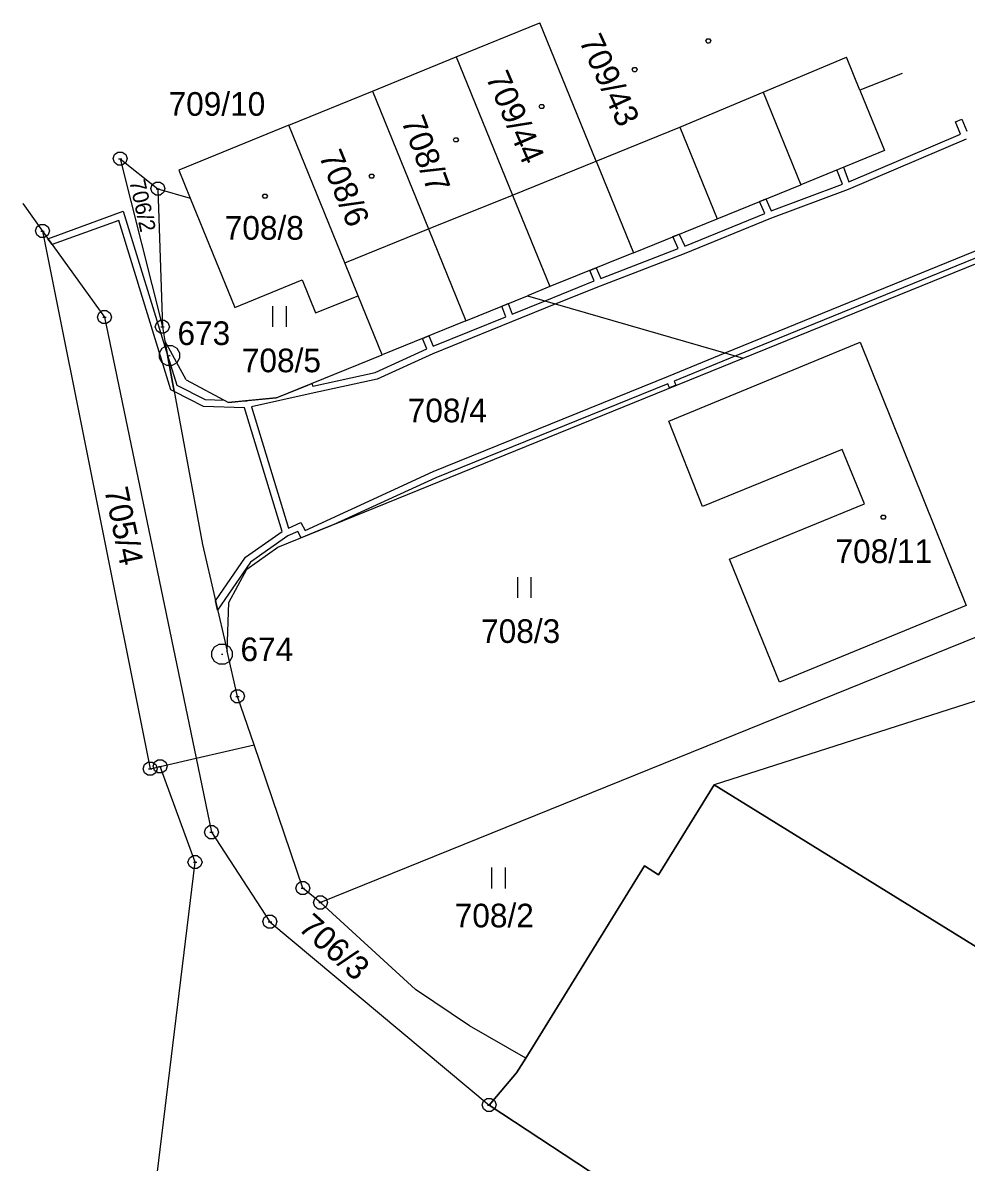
# Model space of a CAD drawing. Extents: x -759699 to -757730, y -1172308 to -1170857.
# Drawn here: x -758034.7 to -757966.9, y -1171071.6 to -1170989.6 of the extents above; entities that cross this region are included whole.
import ezdxf

# ---------------------------------------------------------------- set-up
doc = ezdxf.new("R2010")
doc.units = 0
for name, color, linetype in [('Vrstva 1', 7, 'Continuous'), ('Vrstva 11', 7, 'Continuous'), ('Vrstva 12', 7, 'Continuous'), ('Vrstva 13', 7, 'Continuous'), ('Vrstva 2', 7, 'Continuous'), ('Vrstva 3', 7, 'Continuous'), ('Vrstva 4', 7, 'Continuous'), ('Vrstva 5', 7, 'Continuous'), ('Vrstva 8', 7, 'Continuous')]:
    doc.layers.add(name, color=color, linetype=linetype)

msp = doc.modelspace()

# ---------------------------------------------------------------- linework, layer by layer
at = {"layer": 'Vrstva 1'}
for p, q in [((-758003.56, -1170992.08), (-757997.55, -1170989.62)), ((-757997.55, -1170989.62), (-757997.55, -1170989.62)), ((-757993.5, -1170999.58), (-757997.55, -1170989.62)), ((-757997.55, -1170989.62), (-757997.55, -1170989.62)), ((-758009.59, -1170994.53), (-758003.56, -1170992.08)), ((-758003.56, -1170992.08), (-758003.56, -1170992.08)), ((-758003.56, -1170992.08), (-757999.52, -1171002.02)), ((-757974.53, -1170994.46), (-757975.49, -1170992.1)), ((-757975.49, -1170992.1), (-757975.49, -1170992.1)), ((-757971.49, -1170993.27), (-757974.53, -1170994.46)), ((-757971.49, -1170993.27), (-757971.49, -1170993.27)), ((-758015.61, -1170996.99), (-758009.59, -1170994.53)), ((-758009.59, -1170994.53), (-758005.55, -1171004.46)), ((-758009.59, -1170994.53), (-758009.59, -1170994.53)), ((-757981.48, -1170994.62), (-757981.48, -1170994.62)), ((-757981.48, -1170994.62), (-757978.78, -1171001.27)), ((-757974.53, -1170994.46), (-757972.76, -1170998.82)), ((-758015.61, -1170996.99), (-758023.51, -1171000.23)), ((-758011.58, -1171006.89), (-758015.61, -1170996.99)), ((-758015.61, -1170996.99), (-758015.61, -1170996.99)), ((-757987.48, -1170997.14), (-757987.48, -1170997.14)), ((-757987.48, -1170997.14), (-757984.8, -1171003.72)), ((-757972.76, -1170998.82), (-757978.78, -1171001.27)), ((-757972.76, -1170998.82), (-757972.76, -1170998.82)), ((-758027.74, -1170999.4), (-758027.74, -1170999.4)), ((-758027.74, -1170999.4), (-758027.74, -1170999.4)), ((-758027.74, -1170999.4), (-758024.7, -1171011.5)), ((-758027.74, -1170999.4), (-758025.02, -1171001.56)), ((-758027.74, -1170999.4), (-758027.74, -1170999.4)), ((-758027.74, -1170999.4), (-758027.74, -1170999.4)), ((-757993.5, -1170999.58), (-757990.82, -1171006.17)), ((-758023.51, -1171000.23), (-758022.7, -1171002.23)), ((-758025.02, -1171001.56), (-758024.7, -1171011.5)), ((-758025.02, -1171001.56), (-758022.7, -1171002.23)), ((-757984.8, -1171003.72), (-757978.78, -1171001.27)), ((-758022.7, -1171002.23), (-758019.5, -1171010.1)), ((-757999.52, -1171002.02), (-757996.84, -1171008.61)), ((-758034.74, -1171002.63), (-758033.32, -1171004.61)), ((-758034.74, -1171002.63), (-758034.74, -1171002.63)), ((-757990.82, -1171006.17), (-757984.8, -1171003.72)), ((-758033.32, -1171004.61), (-758028.86, -1171010.81)), ((-758033.32, -1171004.61), (-758025.58, -1171043.31)), ((-758005.55, -1171004.46), (-758002.87, -1171011.06)), ((-757990.82, -1171006.17), (-757996.84, -1171008.61)), ((-758010.62, -1171009.26), (-758011.58, -1171006.89)), ((-757982.93, -1171013.75), (-757966.1, -1171006.91)), ((-758019.5, -1171010.1), (-758014.65, -1171008.13)), ((-758014.65, -1171008.13), (-758013.69, -1171010.5)), ((-757996.84, -1171008.61), (-757998.44, -1171009.26)), ((-758013.69, -1171010.5), (-758010.62, -1171009.26)), ((-758008.89, -1171013.51), (-758010.62, -1171009.26)), ((-758002.87, -1171011.06), (-757998.44, -1171009.26)), ((-757998.44, -1171009.26), (-757982.93, -1171013.75)), ((-758028.86, -1171010.81), (-758022.28, -1171042.55)), ((-758024.7, -1171011.5), (-758024.52, -1171012.5)), ((-758002.87, -1171011.06), (-758008.89, -1171013.51)), ((-758022.99, -1171015.32), (-758024.52, -1171012.5)), ((-758024.52, -1171012.5), (-758021.82, -1171027.17)), ((-757988.28, -1171018.28), (-757974.5, -1171012.6)), ((-757974.5, -1171012.6), (-757966.89, -1171031.56)), ((-758016.51, -1171016.61), (-758008.89, -1171013.51)), ((-758016.39, -1171027.36), (-757982.93, -1171013.75)), ((-758022.99, -1171015.32), (-758019.95, -1171016.94)), ((-758016.51, -1171016.61), (-758019.95, -1171016.94)), ((-757985.84, -1171024.44), (-757988.28, -1171018.28)), ((-757975.81, -1171020.32), (-757985.84, -1171024.44)), ((-757974.2, -1171024.23), (-757975.81, -1171020.32)), ((-757983.9, -1171028.22), (-757974.2, -1171024.23)), ((-758021.82, -1171027.17), (-758020.05, -1171034.85)), ((-758018.62, -1171028.95), (-758016.39, -1171027.36)), ((-757980.32, -1171037.07), (-757983.9, -1171028.22)), ((-758019.92, -1171031.35), (-758018.62, -1171028.95)), ((-757956.71, -1171029.99), (-758013.33, -1171052.94)), ((-758020.05, -1171034.85), (-758019.92, -1171031.35)), ((-757966.89, -1171031.56), (-757980.32, -1171037.07)), ((-758019.3, -1171038.1), (-758020.05, -1171034.85)), ((-757954.81, -1171034.78), (-757985.01, -1171044.46)), ((-758018.11, -1171041.59), (-758019.3, -1171038.1)), ((-758022.28, -1171042.55), (-758018.11, -1171041.59)), ((-758014.6, -1171051.9), (-758018.11, -1171041.59)), ((-758024.86, -1171043.14), (-758022.28, -1171042.55)), ((-758022.28, -1171042.55), (-758021.17, -1171047.88)), ((-758025.58, -1171043.31), (-758024.86, -1171043.14)), ((-758022.35, -1171050.03), (-758024.86, -1171043.14)), ((-757989.01, -1171050.93), (-757985.01, -1171044.46)), ((-757985.01, -1171044.46), (-757962.39, -1171058.46)), ((-758021.17, -1171047.88), (-758016.96, -1171054.32)), ((-758030.77, -1171119.52), (-758022.35, -1171050.03)), ((-757998.57, -1171064.13), (-757990.03, -1171050.3)), ((-757990.03, -1171050.3), (-757989.01, -1171050.93)), ((-758013.33, -1171052.94), (-758014.6, -1171051.9)), ((-758006.5, -1171059.2), (-758013.33, -1171052.94)), ((-758016.96, -1171054.32), (-758001.2, -1171067.51)), ((-758002.6, -1171061.8), (-758006.5, -1171059.2)), ((-757998.57, -1171064.13), (-758002.6, -1171061.8)), ((-757999.22, -1171065.2), (-757998.57, -1171064.13)), ((-758001.2, -1171067.51), (-757999.22, -1171065.2)), ((-757977.68, -1171082.98), (-758001.2, -1171067.51))]:
    msp.add_line(p, q, dxfattribs=at)
at = {"layer": 'Vrstva 11'}
for p, q in [((-757985.01, -1171044.46), (-757989.01, -1171050.93)), ((-757962.39, -1171058.46), (-757985.01, -1171044.46)), ((-757990.03, -1171050.3), (-757998.57, -1171064.13)), ((-757989.01, -1171050.93), (-757990.03, -1171050.3)), ((-757998.57, -1171064.13), (-757999.22, -1171065.2)), ((-757999.22, -1171065.2), (-758001.2, -1171067.51)), ((-758001.2, -1171067.51), (-757977.68, -1171082.98))]:
    msp.add_line(p, q, dxfattribs=at)
at = {"layer": 'Vrstva 12'}
for p, q in [((-758003.56, -1170992.08), (-757997.55, -1170989.62)), ((-757997.55, -1170989.62), (-757997.55, -1170989.62)), ((-757993.5, -1170999.58), (-757997.55, -1170989.62)), ((-757993.5, -1170999.58), (-757997.55, -1170989.62)), ((-758009.59, -1170994.53), (-758003.56, -1170992.08)), ((-758003.56, -1170992.08), (-757999.52, -1171002.02)), ((-758003.56, -1170992.08), (-757999.52, -1171002.02)), ((-757981.48, -1170994.62), (-757975.49, -1170992.1)), ((-757974.53, -1170994.46), (-757975.49, -1170992.1)), ((-757975.49, -1170992.1), (-757975.49, -1170992.1)), ((-757975.49, -1170992.1), (-757975.49, -1170992.1)), ((-757971.49, -1170993.27), (-757974.53, -1170994.46)), ((-757971.49, -1170993.27), (-757971.49, -1170993.27)), ((-758015.61, -1170996.99), (-758009.59, -1170994.53)), ((-758009.59, -1170994.53), (-758005.55, -1171004.46)), ((-758009.59, -1170994.53), (-758005.55, -1171004.46)), ((-757987.48, -1170997.14), (-757981.48, -1170994.62)), ((-757981.48, -1170994.62), (-757981.48, -1170994.62)), ((-757981.48, -1170994.62), (-757981.48, -1170994.62)), ((-758015.61, -1170996.99), (-758023.51, -1171000.23)), ((-758011.58, -1171006.89), (-758015.61, -1170996.99)), ((-758011.58, -1171006.89), (-758015.61, -1170996.99)), ((-757993.5, -1170999.58), (-757987.48, -1170997.14)), ((-757987.48, -1170997.14), (-757987.48, -1170997.14)), ((-757987.48, -1170997.14), (-757987.48, -1170997.14)), ((-757999.52, -1171002.02), (-757993.5, -1170999.58)), ((-758023.51, -1171000.23), (-758022.7, -1171002.23)), ((-758022.7, -1171002.23), (-758019.5, -1171010.1)), ((-758005.55, -1171004.46), (-757999.52, -1171002.02)), ((-758011.58, -1171006.89), (-758005.55, -1171004.46)), ((-758010.62, -1171009.26), (-758011.58, -1171006.89)), ((-758019.5, -1171010.1), (-758014.65, -1171008.13)), ((-758014.65, -1171008.13), (-758013.69, -1171010.5)), ((-758013.69, -1171010.5), (-758010.62, -1171009.26)), ((-757988.28, -1171018.28), (-757974.5, -1171012.6)), ((-757974.5, -1171012.6), (-757966.89, -1171031.56)), ((-757985.84, -1171024.44), (-757988.28, -1171018.28)), ((-757975.81, -1171020.32), (-757985.84, -1171024.44)), ((-757974.2, -1171024.23), (-757975.81, -1171020.32)), ((-757983.9, -1171028.22), (-757974.2, -1171024.23)), ((-757980.32, -1171037.07), (-757983.9, -1171028.22)), ((-757966.89, -1171031.56), (-757980.32, -1171037.07))]:
    msp.add_line(p, q, dxfattribs=at)
at = {"layer": 'Vrstva 13'}
for p, q in [((-757967.65, -1170996.74), (-757967.19, -1170996.55)), ((-757967.3, -1170997.63), (-757967.65, -1170996.74)), ((-757967.19, -1170996.55), (-757966.84, -1170997.43)), ((-757966.88, -1170997.99), (-757975.37, -1171001.62)), ((-757975.32, -1171001.06), (-757967.3, -1170997.63)), ((-757976.18, -1171000.21), (-757975.72, -1171000.02)), ((-757975.72, -1171000.02), (-757975.32, -1171001.06)), ((-757975.78, -1171001.24), (-757976.18, -1171000.21)), ((-757975.37, -1171001.62), (-757980.95, -1171003.7)), ((-757980.91, -1171003.15), (-757975.78, -1171001.24)), ((-757981.75, -1171002.48), (-757981.29, -1171002.29)), ((-757981.37, -1171003.34), (-757981.75, -1171002.48)), ((-757981.29, -1171002.29), (-757980.91, -1171003.15)), ((-758032.93, -1171005.16), (-758027.51, -1171003.18)), ((-758027.51, -1171003.18), (-758024.33, -1171013.55)), ((-757987.13, -1171005.69), (-757981.37, -1171003.34)), ((-758027.83, -1171003.84), (-758032.62, -1171005.58)), ((-758024.09, -1171016.03), (-758027.83, -1171003.84)), ((-757980.95, -1171003.7), (-757987.17, -1171006.24)), ((-757987.98, -1171005.01), (-757987.52, -1171004.83)), ((-757987.52, -1171004.83), (-757987.13, -1171005.69)), ((-758032.62, -1171005.58), (-758032.93, -1171005.16)), ((-757987.6, -1171005.87), (-757987.98, -1171005.01)), ((-757984.22, -1171013.38), (-757963.99, -1171005.12)), ((-757963.81, -1171005.58), (-757983.45, -1171013.6)), ((-757987.17, -1171006.24), (-757993.22, -1171008.57)), ((-757993.17, -1171008.02), (-757987.6, -1171005.87)), ((-757993.96, -1171007.44), (-757993.5, -1171007.25)), ((-757993.64, -1171008.2), (-757993.96, -1171007.44)), ((-757993.5, -1171007.25), (-757993.17, -1171008.02)), ((-757997.17, -1171009.63), (-757993.64, -1171008.2)), ((-757993.22, -1171008.57), (-757996.39, -1171009.85)), ((-758000.29, -1171010.01), (-757999.83, -1171009.82)), ((-757999.83, -1171009.82), (-757999.53, -1171010.58)), ((-757996.39, -1171009.85), (-757999.58, -1171011.14)), ((-757999.53, -1171010.58), (-757997.17, -1171009.63)), ((-757999.99, -1171010.77), (-758000.29, -1171010.01)), ((-757999.58, -1171011.14), (-758005.25, -1171013.45)), ((-758005.22, -1171012.9), (-757999.99, -1171010.77)), ((-758005.99, -1171012.33), (-758005.54, -1171012.15)), ((-758005.67, -1171013.09), (-758005.99, -1171012.33)), ((-758005.54, -1171012.15), (-758005.22, -1171012.9)), ((-758009.4, -1171014.79), (-758005.67, -1171013.09)), ((-758024.33, -1171013.55), (-758023.85, -1171016.16)), ((-758023.85, -1171016.16), (-758024.33, -1171013.55)), ((-758024.33, -1171013.55), (-758023.67, -1171015.69)), ((-758005.25, -1171013.45), (-758009.24, -1171015.27)), ((-757988.29, -1171015.04), (-757984.22, -1171013.38)), ((-757983.45, -1171013.6), (-757987.88, -1171015.41)), ((-758013.88, -1171015.76), (-758009.4, -1171014.79)), ((-758014.41, -1171015.76), (-758013.95, -1171015.57)), ((-758009.24, -1171015.27), (-758013.99, -1171016.29)), ((-758013.95, -1171015.57), (-758013.88, -1171015.76)), ((-758005.23, -1171021.92), (-757988.29, -1171015.04)), ((-757988.34, -1171015.6), (-758005.03, -1171022.38)), ((-757988.22, -1171015.9), (-757988.34, -1171015.6)), ((-757987.88, -1171015.41), (-757987.76, -1171015.71)), ((-758023.85, -1171016.16), (-758024.09, -1171016.03)), ((-758021.75, -1171017.24), (-758023.85, -1171016.16)), ((-758023.67, -1171015.69), (-758021.63, -1171016.74)), ((-758013.99, -1171016.29), (-758018.29, -1171017.26)), ((-758016.51, -1171016.61), (-758014.41, -1171015.76)), ((-757987.76, -1171015.71), (-757988.22, -1171015.9)), ((-758018.8, -1171017.32), (-758021.75, -1171017.24)), ((-758021.63, -1171016.74), (-758020.25, -1171016.78)), ((-758020.25, -1171016.78), (-758019.95, -1171016.94)), ((-758019.95, -1171016.94), (-758018.76, -1171016.83)), ((-758018.76, -1171016.83), (-758018.63, -1171016.83)), ((-758018.63, -1171016.83), (-758018.52, -1171016.8)), ((-758018.52, -1171016.8), (-758016.51, -1171016.61)), ((-758018.29, -1171017.26), (-758015.63, -1171025.98)), ((-758016.08, -1171026.22), (-758018.8, -1171017.32)), ((-758014.43, -1171026.15), (-758005.23, -1171021.92)), ((-758005.03, -1171022.38), (-758012.42, -1171025.74)), ((-758018.73, -1171028.07), (-758016.08, -1171026.22)), ((-758014.96, -1171026.22), (-758015.67, -1171026.54)), ((-758015.63, -1171025.98), (-758014.74, -1171025.58)), ((-758014.72, -1171026.68), (-758014.96, -1171026.22)), ((-758014.74, -1171025.58), (-758014.43, -1171026.15)), ((-758013.45, -1171026.16), (-758014.72, -1171026.68)), ((-758012.42, -1171025.74), (-758013.45, -1171026.16)), ((-758015.67, -1171026.54), (-758018.37, -1171028.43)), ((-758020.88, -1171031.23), (-758018.73, -1171028.07)), ((-758018.37, -1171028.43), (-758020.73, -1171031.89)), ((-758020.73, -1171031.89), (-758020.88, -1171031.23))]:
    msp.add_line(p, q, dxfattribs=at)
at = {"layer": 'Vrstva 3'}
for p, q in [((-758016.78, -1171010.01), (-758016.78, -1171011.51)), ((-758015.78, -1171011.51), (-758015.78, -1171010.01)), ((-757999.17, -1171029.51), (-757999.17, -1171031.01)), ((-757998.17, -1171031.01), (-757998.17, -1171029.51)), ((-758001.03, -1171050.42), (-758001.03, -1171051.92)), ((-758000.03, -1171051.92), (-758000.03, -1171050.42))]:
    msp.add_line(p, q, dxfattribs=at)
at = {"layer": 'Vrstva 4'}
for p, q in [((-757981.48, -1170994.62), (-757975.49, -1170992.1)), ((-757987.48, -1170997.14), (-757981.48, -1170994.62)), ((-757993.5, -1170999.58), (-757987.48, -1170997.14)), ((-757999.52, -1171002.02), (-757993.5, -1170999.58)), ((-758005.55, -1171004.46), (-757999.52, -1171002.02)), ((-758011.58, -1171006.89), (-758005.55, -1171004.46))]:
    msp.add_line(p, q, dxfattribs=at)
at = {"layer": 'Vrstva 5'}
for points in [[(-757985.34, -1170990.78), (-757985.25, -1170990.93), (-757985.34, -1170991.08), (-757985.52, -1170991.08), (-757985.61, -1170990.93), (-757985.52, -1170990.78)], [(-757990.64, -1170992.84), (-757990.55, -1170992.99), (-757990.64, -1170993.14), (-757990.82, -1170993.14), (-757990.91, -1170992.99), (-757990.82, -1170992.84)], [(-757997.34, -1170995.49), (-757997.25, -1170995.64), (-757997.34, -1170995.79), (-757997.52, -1170995.79), (-757997.61, -1170995.64), (-757997.52, -1170995.49)], [(-758003.5, -1170997.89), (-758003.41, -1170998.04), (-758003.5, -1170998.19), (-758003.68, -1170998.19), (-758003.77, -1170998.04), (-758003.68, -1170997.89)], [(-758009.56, -1171000.51), (-758009.47, -1171000.66), (-758009.56, -1171000.81), (-758009.74, -1171000.81), (-758009.83, -1171000.66), (-758009.74, -1171000.51)], [(-758017.23, -1171001.95), (-758017.14, -1171002.1), (-758017.23, -1171002.25), (-758017.41, -1171002.25), (-758017.5, -1171002.1), (-758017.41, -1171001.95)], [(-757972.75, -1171025.05), (-757972.66, -1171025.2), (-757972.75, -1171025.35), (-757972.93, -1171025.35), (-757973.02, -1171025.2), (-757972.93, -1171025.05)]]:
    msp.add_lwpolyline(points, close=True, dxfattribs=at)
at = {"layer": 'Vrstva 8'}
for p, q in [((-758027.86, -1170999.4), (-758027.62, -1170999.4)), ((-758025.14, -1171001.56), (-758024.9, -1171001.56)), ((-758033.44, -1171004.61), (-758033.2, -1171004.61)), ((-758028.98, -1171010.81), (-758028.74, -1171010.81)), ((-758024.82, -1171011.5), (-758024.58, -1171011.5)), ((-758024.23, -1171013.56), (-758024.13, -1171013.56)), ((-758020.46, -1171035.05), (-758020.36, -1171035.05)), ((-758019.42, -1171038.1), (-758019.18, -1171038.1)), ((-758025.7, -1171043.31), (-758025.46, -1171043.31)), ((-758024.98, -1171043.14), (-758024.74, -1171043.14)), ((-758021.29, -1171047.88), (-758021.05, -1171047.88)), ((-758022.47, -1171050.03), (-758022.23, -1171050.03)), ((-758014.72, -1171051.9), (-758014.48, -1171051.9)), ((-758013.45, -1171052.94), (-758013.21, -1171052.94)), ((-758017.08, -1171054.32), (-758016.84, -1171054.32)), ((-758001.32, -1171067.51), (-758001.08, -1171067.51))]:
    msp.add_line(p, q, dxfattribs=at)
for points in [[(-758027.59, -1170998.92), (-758027.34, -1170999.1), (-758027.24, -1170999.39), (-758027.34, -1170999.68), (-758027.59, -1170999.86), (-758027.9, -1170999.86), (-758028.15, -1170999.68), (-758028.25, -1170999.39), (-758028.15, -1170999.1), (-758027.9, -1170998.92)], [(-758024.87, -1171001.08), (-758024.62, -1171001.26), (-758024.52, -1171001.55), (-758024.62, -1171001.84), (-758024.87, -1171002.02), (-758025.18, -1171002.02), (-758025.43, -1171001.84), (-758025.53, -1171001.55), (-758025.43, -1171001.26), (-758025.18, -1171001.08)], [(-758033.17, -1171004.13), (-758032.92, -1171004.31), (-758032.82, -1171004.6), (-758032.92, -1171004.89), (-758033.17, -1171005.07), (-758033.48, -1171005.07), (-758033.73, -1171004.89), (-758033.83, -1171004.6), (-758033.73, -1171004.31), (-758033.48, -1171004.13)], [(-758028.71, -1171010.33), (-758028.46, -1171010.51), (-758028.36, -1171010.8), (-758028.46, -1171011.09), (-758028.71, -1171011.27), (-758029.02, -1171011.27), (-758029.27, -1171011.09), (-758029.37, -1171010.8), (-758029.27, -1171010.51), (-758029.02, -1171010.33)], [(-758024.55, -1171011.02), (-758024.3, -1171011.2), (-758024.2, -1171011.49), (-758024.3, -1171011.78), (-758024.55, -1171011.96), (-758024.86, -1171011.96), (-758025.11, -1171011.78), (-758025.21, -1171011.49), (-758025.11, -1171011.2), (-758024.86, -1171011.02)], [(-758023.99, -1171012.84), (-758023.65, -1171013.03), (-758023.46, -1171013.37), (-758023.46, -1171013.76), (-758023.65, -1171014.1), (-758023.99, -1171014.29), (-758024.38, -1171014.29), (-758024.72, -1171014.1), (-758024.91, -1171013.76), (-758024.91, -1171013.37), (-758024.72, -1171013.03), (-758024.38, -1171012.84)], [(-758020.22, -1171034.33), (-758019.88, -1171034.52), (-758019.69, -1171034.86), (-758019.69, -1171035.25), (-758019.88, -1171035.59), (-758020.22, -1171035.78), (-758020.61, -1171035.78), (-758020.95, -1171035.59), (-758021.14, -1171035.25), (-758021.14, -1171034.86), (-758020.95, -1171034.52), (-758020.61, -1171034.33)], [(-758019.15, -1171037.62), (-758018.9, -1171037.8), (-758018.8, -1171038.09), (-758018.9, -1171038.38), (-758019.15, -1171038.56), (-758019.46, -1171038.56), (-758019.71, -1171038.38), (-758019.81, -1171038.09), (-758019.71, -1171037.8), (-758019.46, -1171037.62)], [(-758024.71, -1171042.66), (-758024.46, -1171042.84), (-758024.36, -1171043.13), (-758024.46, -1171043.42), (-758024.71, -1171043.6), (-758025.02, -1171043.6), (-758025.27, -1171043.42), (-758025.37, -1171043.13), (-758025.27, -1171042.84), (-758025.02, -1171042.66)], [(-758025.43, -1171042.83), (-758025.18, -1171043.01), (-758025.08, -1171043.3), (-758025.18, -1171043.59), (-758025.43, -1171043.77), (-758025.74, -1171043.77), (-758025.99, -1171043.59), (-758026.09, -1171043.3), (-758025.99, -1171043.01), (-758025.74, -1171042.83)], [(-758021.02, -1171047.4), (-758020.77, -1171047.58), (-758020.67, -1171047.87), (-758020.77, -1171048.16), (-758021.02, -1171048.34), (-758021.33, -1171048.34), (-758021.58, -1171048.16), (-758021.68, -1171047.87), (-758021.58, -1171047.58), (-758021.33, -1171047.4)], [(-758022.2, -1171049.55), (-758021.95, -1171049.73), (-758021.85, -1171050.02), (-758021.95, -1171050.31), (-758022.2, -1171050.49), (-758022.51, -1171050.49), (-758022.76, -1171050.31), (-758022.86, -1171050.02), (-758022.76, -1171049.73), (-758022.51, -1171049.55)], [(-758014.45, -1171051.42), (-758014.2, -1171051.6), (-758014.1, -1171051.89), (-758014.2, -1171052.18), (-758014.45, -1171052.36), (-758014.76, -1171052.36), (-758015.01, -1171052.18), (-758015.11, -1171051.89), (-758015.01, -1171051.6), (-758014.76, -1171051.42)], [(-758013.18, -1171052.46), (-758012.93, -1171052.64), (-758012.83, -1171052.93), (-758012.93, -1171053.22), (-758013.18, -1171053.4), (-758013.49, -1171053.4), (-758013.74, -1171053.22), (-758013.84, -1171052.93), (-758013.74, -1171052.64), (-758013.49, -1171052.46)], [(-758016.81, -1171053.84), (-758016.56, -1171054.02), (-758016.46, -1171054.31), (-758016.56, -1171054.6), (-758016.81, -1171054.78), (-758017.12, -1171054.78), (-758017.37, -1171054.6), (-758017.47, -1171054.31), (-758017.37, -1171054.02), (-758017.12, -1171053.84)], [(-758001.05, -1171067.03), (-758000.8, -1171067.21), (-758000.7, -1171067.5), (-758000.8, -1171067.79), (-758001.05, -1171067.97), (-758001.36, -1171067.97), (-758001.61, -1171067.79), (-758001.71, -1171067.5), (-758001.61, -1171067.21), (-758001.36, -1171067.03)]]:
    msp.add_lwpolyline(points, close=True, dxfattribs=at)

# ---------------------------------------------------------------- texts
at = {"layer": 'Vrstva 2'}
for s, height, rotation, p in [('709/43', 1.7, 294.6149, (-757994.761, -1170990.916)), ('709/44', 1.7, 293.2398, (-758001.466, -1170993.538)), ('708/7', 1.7, 290.5469, (-758007.537, -1170996.682)), ('708/6', 1.7, 292.20848, (-758013.47, -1170999.19)), ('706/2', 1.14, 282.4109, (-758027.083, -1171001.032)), ('705/4', 1.7, 281.89524, (-758028.885, -1171023.218)), ('706/3', 1.7, 318.04887, (-758015.008, -1171054.846))]:
    msp.add_text(s, height=height, rotation=rotation, dxfattribs=at).set_placement(p)
for s, p in [('709/10', (-758024.253, -1170996.31)), ('708/8', (-758020.213, -1171005.23)), ('708/5', (-758018.983, -1171014.77)), ('708/4', (-758007.053, -1171018.37)), ('708/11', (-757976.283, -1171028.5)), ('708/3', (-758001.773, -1171034.25)), ('708/2', (-758003.673, -1171054.72))]:
    msp.add_text(s, height=1.7, dxfattribs=at).set_placement(p)
at = {"layer": 'Vrstva 8'}
for s, p in [('673', (-758023.614, -1171012.81)), ('674', (-758019.084, -1171035.56))]:
    msp.add_text(s, height=1.7, dxfattribs=at).set_placement(p)

doc.saveas('drawing.dxf')
